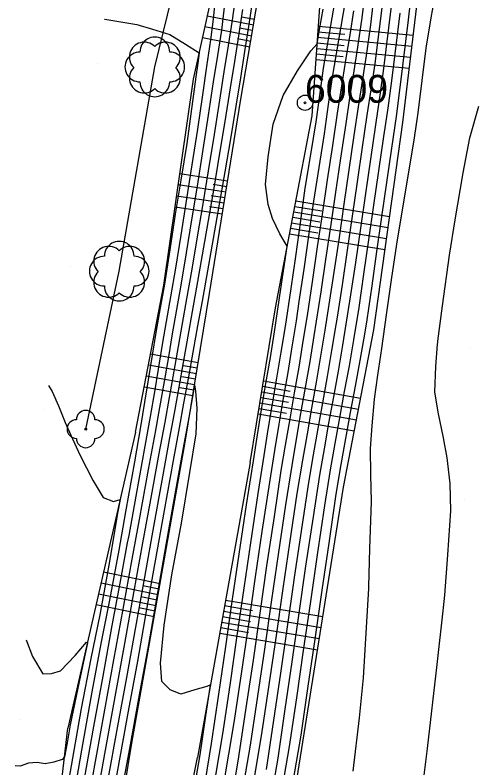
# Model space of a CAD drawing. Extents: x -448957 to -448612, y -1107690 to -1107245.
# Drawn here: x -448743.82 to -448719.11, y -1107510.01 to -1107469.55 of the extents above; entities that cross this region are included whole.
import ezdxf

# ---------------------------------------------------------------- set-up
doc = ezdxf.new("R2010")
doc.units = 0
for name, color, linetype in [('22', 7, 'Continuous'), ('63', 7, 'Continuous'), ('Default', 7, 'Continuous'), ('Vrstva 1', 7, 'Continuous'), ('Vrstva 14', 7, 'Continuous'), ('Vrstva 15', 7, 'Continuous'), ('Vrstva 16', 7, 'Continuous'), ('Vrstva 17', 7, 'Continuous'), ('Vrstva 21', 7, 'Continuous'), ('Vrstva 22', 7, 'Continuous'), ('Vrstva 63', 7, 'Continuous')]:
    doc.layers.add(name, color=color, linetype=linetype)

# ---------------------------------------------------------------- blocks, each defined once
blk = doc.blocks.new('POINT_DISPLAY')
at = {"layer": 'Default'}
blk.add_line((0, 0), (0, 0), dxfattribs=at)
blk = doc.blocks.new('PPBP$7')
at = {"layer": '63'}
for radius in [4.12, 0.5]:
    blk.add_circle((0, 0), radius, dxfattribs=at)
blk = doc.blocks.new('KER')
at = {"layer": 'Default'}
for centre, start, end in [((-5.66, 5.31), 44.9958, 225.0042), ((0, 8), 359.9958, 180.0042), ((5.66, 5.31), 314.9989, 135.0011), ((-8, 0), 89.9989, 270.0011), ((8, 0), 269.9989, 90.0011), ((-5.66, -6), 134.9989, 315.0011), ((5.66, -6), 224.9958, 45.0042), ((0, -8), 179.9958, 0.0042)]:
    blk.add_arc(centre, 8, start, end, dxfattribs=at)
blk = doc.blocks.new('STROM$5')
at = {"layer": '22'}
blk.add_circle((0, 0), 0.5, dxfattribs=at)
for centre, start, end in [((0, 5), 0, 180), ((-5, 0), 90, 270), ((5, 0), 270, 90), ((0, -5), 180, 0)]:
    blk.add_arc(centre, 5, start, end, dxfattribs=at)

msp = doc.modelspace()

# ---------------------------------------------------------------- linework, layer by layer
at = {"layer": 'Vrstva 14'}
for p, q in [((-448734.234, -1107472.988), (-448732.359, -1107464.446)), ((-448722.982, -1107475.329), (-448721.738, -1107464.829)), ((-448731.678, -1107474.069), (-448730.236, -1107465.588)), ((-448727.858, -1107474.971), (-448727.235, -1107466.085)), ((-448735.826, -1107484.058), (-448734.234, -1107472.988)), ((-448733.374, -1107484.507), (-448731.678, -1107474.069)), ((-448729.827, -1107485.277), (-448727.858, -1107474.971)), ((-448724.549, -1107486.465), (-448722.982, -1107475.329)), ((-448737.347, -1107491.968), (-448735.826, -1107484.058)), ((-448734.671, -1107492.503), (-448733.374, -1107484.507)), ((-448731.182, -1107493.587), (-448729.827, -1107485.277)), ((-448726.173, -1107494.917), (-448724.549, -1107486.465)), ((-448737.347, -1107491.968), (-448740.976, -1107507.868)), ((-448737.547, -1107508.673), (-448734.671, -1107492.503)), ((-448731.182, -1107493.587), (-448734.017, -1107509.453)), ((-448728.681, -1107510.64), (-448726.173, -1107494.917)), ((-448743.237, -1107527.444), (-448740.976, -1107507.868)), ((-448740.709, -1107527.734), (-448737.547, -1107508.673)), ((-448737.861, -1107528.552), (-448734.017, -1107509.453))]:
    msp.add_line(p, q, dxfattribs=at)
at = {"layer": 'Vrstva 15'}
for p, q in [((-448731.001, -1107470.088), (-448733.491, -1107469.604)), ((-448730.951, -1107469.793), (-448731.654, -1107469.656)), ((-448731.102, -1107470.68), (-448733.62, -1107470.19)), ((-448731.051, -1107470.384), (-448731.763, -1107470.246)), ((-448727.541, -1107470.444), (-448726.093, -1107470.58)), ((-448727.52, -1107470.144), (-448722.425, -1107470.625)), ((-448731.202, -1107471.272), (-448733.748, -1107470.776)), ((-448731.152, -1107470.976), (-448731.872, -1107470.836)), ((-448727.562, -1107470.743), (-448722.495, -1107471.221)), ((-448727.583, -1107471.042), (-448726.143, -1107471.178)), ((-448727.625, -1107471.641), (-448726.193, -1107471.776)), ((-448727.604, -1107471.342), (-448722.566, -1107471.817)), ((-448727.646, -1107471.941), (-448722.636, -1107472.413)), ((-448732.395, -1107478.48), (-448734.967, -1107478.086)), ((-448732.491, -1107479.072), (-448735.053, -1107478.68)), ((-448732.443, -1107478.776), (-448733.178, -1107478.663)), ((-448732.587, -1107479.664), (-448735.138, -1107479.274)), ((-448732.539, -1107479.368), (-448733.271, -1107479.256)), ((-448728.73, -1107479.535), (-448723.691, -1107480.37)), ((-448732.683, -1107480.256), (-448735.223, -1107479.867)), ((-448732.635, -1107479.96), (-448733.364, -1107479.849)), ((-448728.843, -1107480.124), (-448723.775, -1107480.964)), ((-448728.786, -1107479.829), (-448727.338, -1107480.069)), ((-448728.899, -1107480.419), (-448727.443, -1107480.66)), ((-448729.011, -1107481.008), (-448727.547, -1107481.251)), ((-448728.955, -1107480.714), (-448723.859, -1107481.559)), ((-448729.068, -1107481.303), (-448723.942, -1107482.153)), ((-448733.978, -1107488.231), (-448736.541, -1107487.777)), ((-448734.074, -1107488.824), (-448736.654, -1107488.367)), ((-448734.026, -1107488.528), (-448734.758, -1107488.398)), ((-448734.17, -1107489.416), (-448736.768, -1107488.956)), ((-448734.122, -1107489.12), (-448734.859, -1107488.989)), ((-448730.516, -1107489.501), (-448729.031, -1107489.765)), ((-448730.467, -1107489.205), (-448725.253, -1107490.131)), ((-448734.266, -1107490.008), (-448736.881, -1107489.545)), ((-448734.218, -1107489.712), (-448734.96, -1107489.581)), ((-448730.564, -1107489.797), (-448725.367, -1107490.72)), ((-448730.612, -1107490.093), (-448729.132, -1107490.356)), ((-448730.709, -1107490.685), (-448729.233, -1107490.947)), ((-448730.661, -1107490.389), (-448725.48, -1107491.309)), ((-448730.757, -1107490.981), (-448725.593, -1107491.898)), ((-448736.024, -1107500.109), (-448739.064, -1107499.492)), ((-448736.129, -1107500.7), (-448739.198, -1107500.077)), ((-448736.076, -1107500.404), (-448736.945, -1107500.228)), ((-448736.234, -1107501.291), (-448739.331, -1107500.662)), ((-448736.181, -1107500.995), (-448737.058, -1107500.817)), ((-448732.505, -1107500.993), (-448727.283, -1107501.876)), ((-448736.339, -1107501.882), (-448739.465, -1107501.247)), ((-448736.287, -1107501.586), (-448737.172, -1107501.407)), ((-448732.611, -1107501.583), (-448727.377, -1107502.468)), ((-448732.558, -1107501.288), (-448731.063, -1107501.541)), ((-448732.664, -1107501.879), (-448731.165, -1107502.132)), ((-448732.716, -1107502.174), (-448727.472, -1107503.061)), ((-448732.822, -1107502.765), (-448727.567, -1107503.653)), ((-448732.769, -1107502.469), (-448731.268, -1107502.723))]:
    msp.add_line(p, q, dxfattribs=at)
at = {"layer": 'Vrstva 16'}
for points in [[(-448731.331, -1107512.754), (-448730.551, -1107508.168), (-448730.161, -1107505.541), (-448729.794, -1107503.014), (-448729.414, -1107500.374), (-448729.051, -1107497.933), (-448728.651, -1107495.269), (-448728.358, -1107493.466), (-448728.112, -1107492.05), (-448727.867, -1107490.669), (-448727.617, -1107489.27), (-448727.38, -1107487.873), (-448727.152, -1107486.489), (-448726.937, -1107485.103), (-448726.673, -1107483.37), (-448726.39, -1107481.496), (-448726.128, -1107479.707), (-448725.861, -1107477.871), (-448725.591, -1107476.015), (-448725.36, -1107474.474), (-448725.133, -1107473.002), (-448724.932, -1107471.731), (-448724.706, -1107470.069), (-448724.496, -1107468.325)], [(-448725.644, -1107510.181), (-448725.313, -1107507.312), (-448725.093, -1107505.169), (-448724.926, -1107502.468), (-448724.816, -1107500.362), (-448724.812, -1107500.258), (-448724.753, -1107498.237), (-448724.663, -1107495.687), (-448724.702, -1107494.234), (-448724.715, -1107492.84), (-448724.623, -1107491.626), (-448724.496, -1107490.19), (-448724.328, -1107488.893), (-448724.116, -1107487.473), (-448723.854, -1107485.655), (-448723.59, -1107483.779), (-448723.302, -1107481.866), (-448723.003, -1107480.015), (-448722.662, -1107477.989), (-448722.349, -1107476.14), (-448722.155, -1107474.799), (-448721.726, -1107471.327), (-448721.443, -1107469.586), (-448721.174, -1107468.133)], [(-448731.065, -1107468.744), (-448731.279, -1107470.169), (-448731.481, -1107471.512), (-448731.708, -1107472.931), (-448731.949, -1107474.441), (-448732.24, -1107476.202), (-448732.538, -1107477.979), (-448732.842, -1107479.714), (-448733.167, -1107481.558), (-448733.476, -1107483.292), (-448733.767, -1107484.925), (-448734.005, -1107486.251), (-448734.261, -1107487.658), (-448734.504, -1107488.985), (-448734.764, -1107490.399), (-448735.002, -1107491.728), (-448735.318, -1107493.484), (-448735.803, -1107496.17), (-448736.289, -1107498.882), (-448736.766, -1107501.577), (-448737.243, -1107504.267), (-448737.732, -1107506.96), (-448738.421, -1107510.714)], [(-448733.606, -1107510.796), (-448733.253, -1107508.688), (-448732.861, -1107506.036), (-448732.509, -1107503.615), (-448732.125, -1107500.947), (-448731.775, -1107498.529), (-448731.373, -1107495.866), (-448731.014, -1107493.506), (-448730.794, -1107492.116), (-448730.575, -1107490.739), (-448730.337, -1107489.356), (-448730.099, -1107487.958), (-448729.881, -1107486.571), (-448729.441, -1107483.653), (-448729.2, -1107481.996), (-448729.212, -1107481.965), (-448729.253, -1107481.875), (-448729.589, -1107481.306), (-448729.988, -1107480.474), (-448730.221, -1107479.727), (-448730.355, -1107478.648), (-448730.218, -1107477.162), (-448729.946, -1107475.42), (-448729.416, -1107473.868), (-448728.644, -1107472.545), (-448727.922, -1107471.479), (-448727.586, -1107471.093), (-448727.435, -1107470.243), (-448727.256, -1107469.228)], [(-448739.019, -1107469.771), (-448738.99, -1107469.777), (-448737.276, -1107470.052), (-448736.434, -1107470.3), (-448735.505, -1107470.587), (-448734.658, -1107471.107), (-448733.926, -1107471.584), (-448733.999, -1107472.136), (-448734.099, -1107472.861), (-448734.592, -1107476.446), (-448734.91, -1107478.418), (-448735.209, -1107480.249), (-448735.505, -1107482.169), (-448735.788, -1107484.003), (-448736.015, -1107485.285), (-448736.25, -1107486.607), (-448736.453, -1107487.829), (-448736.672, -1107489.154), (-448736.861, -1107490.351), (-448737.075, -1107491.678), (-448737.405, -1107493.564), (-448737.879, -1107496.24), (-448738.247, -1107498.312), (-448738.739, -1107500.985), (-448739.181, -1107503.237), (-448739.685, -1107505.923), (-448740.243, -1107509.06), (-448740.807, -1107512.279)]]:
    msp.add_lwpolyline(points, dxfattribs=at)
at = {"layer": 'Vrstva 17'}
for points in [[(-448731.664, -1107511.687), (-448731.171, -1107508.785), (-448730.778, -1107506.159), (-448730.403, -1107503.618), (-448730.022, -1107500.967), (-448729.666, -1107498.538), (-448729.266, -1107495.875), (-448728.936, -1107493.748), (-448728.693, -1107492.332), (-448728.454, -1107490.958), (-448728.209, -1107489.569), (-448727.969, -1107488.168), (-448727.743, -1107486.783), (-448727.377, -1107484.425), (-448727.115, -1107482.693), (-448726.833, -1107480.813), (-448726.574, -1107479.064), (-448726.306, -1107477.232), (-448726.034, -1107475.377), (-448725.826, -1107474.019), (-448725.597, -1107472.547), (-448725.393, -1107471.284), (-448725.16, -1107469.7), (-448724.956, -1107467.944)], [(-448729.383, -1107513.647), (-448728.45, -1107508.245), (-448728.064, -1107505.617), (-448727.695, -1107503.088), (-448727.313, -1107500.459), (-448726.945, -1107497.931), (-448726.558, -1107495.296), (-448726.288, -1107493.711), (-448726.036, -1107492.297), (-448725.788, -1107490.913), (-448725.533, -1107489.5), (-448725.275, -1107488.106), (-448725.021, -1107486.701), (-448724.898, -1107485.929), (-448724.635, -1107484.105), (-448724.372, -1107482.255), (-448724.103, -1107480.399), (-448723.566, -1107476.708), (-448723.316, -1107475.002), (-448723.104, -1107473.308), (-448722.685, -1107469.813), (-448722.478, -1107468.06)], [(-448733.032, -1107468.266), (-448733.177, -1107469.78), (-448733.312, -1107470.876), (-448733.526, -1107472.32), (-448733.751, -1107473.83), (-448734.018, -1107475.674), (-448734.314, -1107477.593), (-448734.61, -1107479.425), (-448734.918, -1107481.373), (-448735.204, -1107483.154), (-448735.466, -1107484.697), (-448735.698, -1107486.02), (-448735.909, -1107487.257), (-448736.129, -1107488.582), (-448736.328, -1107489.798), (-448736.558, -1107491.126), (-448736.841, -1107492.723), (-448737.324, -1107495.397), (-448737.708, -1107497.512), (-448737.785, -1107497.919), (-448738.191, -1107500.083), (-448738.611, -1107502.351), (-448739.106, -1107505.084), (-448739.594, -1107507.777), (-448739.903, -1107509.485), (-448740.478, -1107512.702)], [(-448731.952, -1107468.37), (-448732.157, -1107469.818), (-448732.372, -1107471.187), (-448732.6, -1107472.605), (-448732.84, -1107474.125), (-448733.127, -1107475.961), (-448733.44, -1107477.921), (-448733.733, -1107479.692), (-448734.029, -1107481.464), (-448734.327, -1107483.201), (-448734.606, -1107484.799), (-448734.837, -1107486.121), (-448735.051, -1107487.366), (-448735.285, -1107488.693), (-448735.537, -1107490.093), (-448735.777, -1107491.421), (-448736.084, -1107493.113), (-448736.571, -1107495.786), (-448736.961, -1107497.912), (-448737.445, -1107500.604), (-448737.931, -1107503.316), (-448738.967, -1107509.045), (-448739.554, -1107512.258)], [(-448733.275, -1107511.878), (-448732.637, -1107508.072), (-448732.243, -1107505.431), (-448731.894, -1107503.015), (-448731.51, -1107500.347), (-448731.154, -1107497.918), (-448730.753, -1107495.255), (-448730.437, -1107493.225), (-448730.21, -1107491.827), (-448729.982, -1107490.441), (-448729.744, -1107489.058), (-448729.511, -1107487.665), (-448729.291, -1107486.279), (-448728.986, -1107484.252), (-448728.731, -1107482.518), (-448728.464, -1107480.588), (-448728.227, -1107478.85), (-448727.926, -1107477.039), (-448727.634, -1107475.293), (-448727.447, -1107473.877), (-448727.246, -1107472.403), (-448727.032, -1107471.162), (-448726.775, -1107469.692), (-448726.566, -1107468.44)], [(-448732.516, -1107468.522), (-448732.635, -1107469.588), (-448732.729, -1107470.359), (-448732.945, -1107471.727), (-448733.17, -1107473.147), (-448733.441, -1107474.933), (-448733.719, -1107476.773), (-448734.035, -1107478.74), (-448734.33, -1107480.563), (-448734.622, -1107482.326), (-448734.912, -1107484.064), (-448735.368, -1107486.687), (-448735.576, -1107487.921), (-448735.802, -1107489.245), (-448736.054, -1107490.645), (-448736.293, -1107491.973), (-448736.656, -1107493.978), (-448737.141, -1107496.651), (-448737.538, -1107498.794), (-448738.028, -1107501.477), (-448738.519, -1107504.2), (-448739.006, -1107506.893), (-448739.703, -1107510.75)], [(-448730.307, -1107510.093), (-448729.544, -1107504.924), (-448729.241, -1107502.808), (-448728.88, -1107500.295), (-448728.807, -1107499.781), (-448728.036, -1107494.664), (-448727.781, -1107493.183), (-448727.532, -1107491.768), (-448727.28, -1107490.38), (-448727.024, -1107488.972), (-448726.79, -1107487.579), (-448726.561, -1107486.194), (-448726.496, -1107485.78), (-448726.232, -1107484.048), (-448725.947, -1107482.179), (-448725.682, -1107480.35), (-448725.416, -1107478.51), (-448725.147, -1107476.654), (-448724.895, -1107474.928), (-448724.668, -1107473.456), (-448724.471, -1107472.178), (-448724.251, -1107470.438), (-448724.036, -1107468.706)], [(-448731.593, -1107469.244), (-448731.816, -1107470.665), (-448732.033, -1107472.037), (-448732.262, -1107473.455), (-448732.551, -1107475.267), (-448732.843, -1107477.081), (-448733.141, -1107478.859), (-448733.436, -1107480.596), (-448733.758, -1107482.43), (-448734.062, -1107484.165), (-448734.294, -1107485.487), (-448734.527, -1107486.81), (-448734.78, -1107488.213), (-448735.02, -1107489.541), (-448735.276, -1107490.948), (-448735.517, -1107492.276), (-448735.896, -1107494.36), (-448736.382, -1107497.039), (-448736.868, -1107499.749), (-448737.348, -1107502.444), (-448737.834, -1107505.156), (-448738.322, -1107507.849), (-448739.377, -1107513.584)], [(-448732.931, -1107512.892), (-448732.021, -1107507.455), (-448731.625, -1107504.826), (-448731.278, -1107502.414), (-448730.895, -1107499.746), (-448730.533, -1107497.307), (-448730.134, -1107494.643), (-448729.859, -1107492.944), (-448729.625, -1107491.537), (-448729.39, -1107490.142), (-448729.151, -1107488.76), (-448728.923, -1107487.373), (-448728.702, -1107485.987), (-448728.544, -1107484.937), (-448728.286, -1107483.203), (-448728.012, -1107481.297), (-448727.767, -1107479.56), (-448727.19, -1107475.931), (-448726.971, -1107474.352), (-448726.756, -1107472.879), (-448726.547, -1107471.627), (-448726.295, -1107470.157), (-448726.085, -1107468.907)], [(-448730.046, -1107511.551), (-448729.688, -1107509.477), (-448729.301, -1107506.849), (-448728.928, -1107504.312), (-448728.549, -1107501.683), (-448728.186, -1107499.165), (-448727.79, -1107496.511), (-448727.445, -1107494.279), (-448727.195, -1107492.865), (-448726.951, -1107491.484), (-448726.693, -1107490.072), (-448726.438, -1107488.68), (-448726.202, -1107487.291), (-448725.772, -1107484.589), (-448725.506, -1107482.844), (-448725.242, -1107481), (-448724.975, -1107479.145), (-448724.441, -1107475.449), (-448724.236, -1107474.101), (-448724.015, -1107472.563), (-448723.585, -1107469.076)], [(-448731.998, -1107510.62), (-448731.791, -1107509.403), (-448731.395, -1107506.777), (-448731.012, -1107504.221), (-448730.629, -1107501.56), (-448730.28, -1107499.144), (-448729.884, -1107496.503), (-448729.514, -1107494.032), (-448729.281, -1107492.663), (-448729.041, -1107491.248), (-448728.798, -1107489.844), (-448728.558, -1107488.463), (-448728.335, -1107487.081), (-448728.112, -1107485.695), (-448727.84, -1107483.888), (-448727.56, -1107482.005), (-448727.307, -1107480.27), (-448727.023, -1107478.399), (-448726.746, -1107476.568), (-448726.495, -1107474.828), (-448726.267, -1107473.356), (-448726.063, -1107472.092), (-448726.026, -1107471.87), (-448725.818, -1107470.614), (-448725.615, -1107469.331)], [(-448729.715, -1107512.599), (-448729.069, -1107508.861), (-448728.682, -1107506.233), (-448728.311, -1107503.7), (-448727.931, -1107501.071), (-448727.566, -1107498.548), (-448727.174, -1107495.904), (-448726.866, -1107493.995), (-448726.615, -1107492.581), (-448726.369, -1107491.199), (-448726.113, -1107489.786), (-448725.856, -1107488.393), (-448725.612, -1107486.996), (-448725.335, -1107485.259), (-448725.071, -1107483.475), (-448724.807, -1107481.627), (-448724.539, -1107479.772), (-448724.003, -1107476.079), (-448723.776, -1107474.551), (-448723.56, -1107472.936), (-448723.134, -1107469.444)], [(-448722.013, -1107511.836), (-448721.662, -1107508.967), (-448721.135, -1107504.449), (-448720.809, -1107501.571), (-448720.728, -1107500.732), (-448720.556, -1107498.553), (-448720.397, -1107496.185), (-448720.446, -1107494.727), (-448720.604, -1107493.352), (-448720.801, -1107492.271), (-448721.082, -1107490.883), (-448721.266, -1107489.789), (-448721.202, -1107488.444), (-448721.114, -1107487.234), (-448721.106, -1107487.149), (-448721.097, -1107487.073), (-448720.847, -1107485.172), (-448720.467, -1107482.445), (-448720.168, -1107480.553), (-448719.735, -1107478.033), (-448719.382, -1107476.151), (-448718.893, -1107474.443)], [(-448742.012, -1107489.457), (-448741.821, -1107489.783), (-448741.479, -1107490.55), (-448741.124, -1107491.45), (-448740.815, -1107492.124), (-448740.341, -1107493.181), (-448739.618, -1107494.586), (-448739.074, -1107495.469), (-448738.529, -1107495.691), (-448738.174, -1107495.592), (-448738.286, -1107496.236), (-448738.435, -1107497.083), (-448738.785, -1107499.113), (-448739.261, -1107501.789), (-448739.74, -1107504.134), (-448740.272, -1107506.807), (-448740.934, -1107510.616)], [(-448734.489, -1107512.905), (-448733.937, -1107509.713), (-448733.869, -1107509.305), (-448733.581, -1107507.339), (-448733.319, -1107505.549), (-448733.519, -1107505.624), (-448734.165, -1107505.812), (-448734.905, -1107506.044), (-448735.476, -1107505.815), (-448735.928, -1107505.361), (-448736.009, -1107504.373), (-448735.809, -1107502.34), (-448735.387, -1107499.628), (-448734.871, -1107496.846), (-448734.431, -1107494.138), (-448734.085, -1107492.062), (-448734.033, -1107490.672), (-448734.097, -1107489.756), (-448734.139, -1107489.527), (-448734.17, -1107489.412), (-448734.251, -1107489.851), (-448734.487, -1107491.179), (-448734.74, -1107492.608), (-448735.224, -1107495.301), (-448735.711, -1107498.014), (-448736.652, -1107503.378), (-448737.143, -1107506.071), (-448737.671, -1107508.962), (-448738.257, -1107512.136)], [(-448743.226, -1107503.129), (-448742.887, -1107504.017), (-448742.331, -1107504.958), (-448741.861, -1107504.934), (-448741.381, -1107504.793), (-448740.591, -1107503.973), (-448739.979, -1107503.251), (-448739.93, -1107503.283), (-448740.376, -1107505.389), (-448740.859, -1107507.691), (-448741.024, -1107508.652), (-448741.155, -1107509.416), (-448741.285, -1107509.561), (-448741.729, -1107509.706), (-448742.196, -1107509.786), (-448742.627, -1107509.709), (-448743.086, -1107509.751), (-448743.542, -1107509.921), (-448743.815, -1107509.893)]]:
    msp.add_lwpolyline(points, dxfattribs=at)
at = {"layer": 'Vrstva 21'}
for p, q in [((-448736.309, -1107472.338), (-448734.666, -1107465.594)), ((-448738.219, -1107483.31), (-448736.309, -1107472.338)), ((-448740.021, -1107491.799), (-448738.219, -1107483.31))]:
    msp.add_line(p, q, dxfattribs=at)

# ---------------------------------------------------------------- block references
at = {"layer": 'Vrstva 1', "xscale": 0.1, "yscale": 0.10000000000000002}
for p in [(-448736.309, -1107472.338), (-448736.309, -1107472.338), (-448734.234, -1107472.988), (-448731.678, -1107474.069), (-448731.678, -1107474.069), (-448727.858, -1107474.971), (-448727.858, -1107474.971), (-448722.982, -1107475.329), (-448738.219, -1107483.31), (-448738.219, -1107483.31), (-448735.826, -1107484.058), (-448733.374, -1107484.507), (-448729.827, -1107485.277), (-448724.549, -1107486.465), (-448740.021, -1107491.799), (-448737.347, -1107491.968), (-448734.671, -1107492.503), (-448731.182, -1107493.587), (-448726.173, -1107494.917), (-448740.976, -1107507.868), (-448737.547, -1107508.673), (-448734.017, -1107509.453)]:
    msp.add_blockref('POINT_DISPLAY', p, dxfattribs=at)
at = {"layer": 'Vrstva 14', "xscale": 0.1, "yscale": 0.10000000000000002}
for p in [(-448739.381, -1107472.145), (-448719.47, -1107475.756), (-448740.824, -1107483.088), (-448719.357, -1107487.477), (-448742.256, -1107490.763), (-448719.675, -1107495.596), (-448743.563, -1107507.432)]:
    msp.add_blockref('POINT_DISPLAY', p, dxfattribs=at)
at = {"layer": 'Vrstva 21', "xscale": 0.1, "yscale": 0.10000000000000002}
for p in [(-448736.309, -1107472.338), (-448736.309, -1107472.338), (-448738.219, -1107483.31), (-448738.219, -1107483.31)]:
    msp.add_blockref('KER', p, dxfattribs=at)
at = {"layer": 'Vrstva 22', "xscale": 0.1, "yscale": 0.10000000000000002}
msp.add_blockref('STROM$5', (-448740.021, -1107491.799), dxfattribs=at)
at = {"layer": 'Vrstva 63', "xscale": 0.1, "yscale": 0.10000000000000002}
msp.add_blockref('PPBP$7', (-448728.238, -1107474.264), dxfattribs=at)

# ---------------------------------------------------------------- texts
at = {"layer": 'Vrstva 63'}
msp.add_text('6009', height=1.5, dxfattribs=at).set_placement((-448728.238, -1107474.264))

doc.saveas('drawing.dxf')
